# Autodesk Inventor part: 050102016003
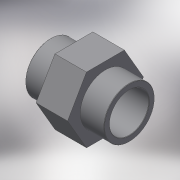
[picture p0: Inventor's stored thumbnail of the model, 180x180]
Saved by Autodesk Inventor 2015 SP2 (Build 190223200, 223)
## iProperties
Created: 2017-10
Part Number: 050102016003
Material: Generic
Description: PLASSON SOCKET ADAPTOR THR-CEM 16-3/8"
Document SubType Name: Modeling
Designer: KIM
Density: 1 g/cm^3
Appearance: Default
Author: KIM
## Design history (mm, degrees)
derived "050102.ipt"
feature "Solid1::050102.ipt"
tag "TaggingFeature1"
body "Solid1"
other parameters: "d1" = 16, "d2" = 25, "d3" = 14.95, "d4" = 14.4, "d5" = 14, "d6" = 13, "d7" = 19.2, "d8" = 19.2, "d10" = 9.1, "d13" = 0, "d14" = 0.16, "d15" = 12, "d_" = 16, "G_" = 14.95, "C_" = 25, "B_" = 12, "l_" = 14, "lt_" = 13
